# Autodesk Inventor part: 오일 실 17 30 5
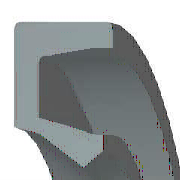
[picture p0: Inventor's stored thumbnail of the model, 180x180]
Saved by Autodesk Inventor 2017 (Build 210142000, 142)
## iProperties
IsCustomPart: 1
Created: 2012-02
Part Number: 오일 실 17 30 5
Material: 고무
Description: 오일 실 - 비스프링, 금속 케이스 GM
Document SubType Name: Modeling
Standard: JIS B 2402
Designer: mduedu
Standards Organization: JIS
Language: ko-KR
Size Designation: 17 30 5 B
Categories: <MemberInstance><Categories><Category DisplayName="샤프트 부품" InternalName="7f7aeb1f-a693-4053-b835-cee3144e0d98" Mnemonic="SHFT"><Category DisplayName="실링" Intern
Density: 0.93 g/cm^3
Appearance: Rubber-Black
Mass: 0.924459 g
Surface Area: 18.6212 cm^2
Volume: 0.994042 cm^3
Author: mduedu
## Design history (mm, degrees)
body "Solid1"
revolve "회전1" stored, may be unused: angle "d27" = 360 deg
fillet "모깎기1" dims "d28" = 0.25 (= 0.05 x b)
chamfer "모따기1" distance "d29" = 0.07143 (= 0.0142857 x b); stored, may be unused: second distance "d30" = 0.25 (= 0.05 x b), angle "d35" = 45 deg
sketch "스케치2"
  geometry: L1 (-9.367, -3.238)-(-10.233, -3.863); L2 (-8.5, -1.625)-(-9.367, -3.238); L3 (-9.15, -1)-(-8.5, -1.625); L4 (-11.317, -3.75)-(-9.15, -1); L5 (-13.075, -3.75)-(-11.317, -3.75); L6 (-14.375, -1.25)-(-13.075, -3.75); L7 (-14.375, 0)-(-14.375, -1.25); L8 (-15, 0)-(-14.375, 0); L9 (-15, -5)-(-15, 0); L10 (-11.129, -5)-(-15, -5); L11 (-10.233, -3.863)-(-11.129, -5); L12 (0, -9.6)-(0, 1.6) reference; L13 (-14, 0)-(-28, 0) reference
  constraints: 22 end point, 3 horizontal, 2 vertical, 1 parallel
  dimensions: "d2" = 5 distance of L9.start L8.start (= b); "d4" = 1 vertical distance of L8.start L3.start (= 0.2 x b); "d6" = 0.625 distance of L8.start L7.start (= 0.125 x b); "d8" = 1.25 distance of L7.start L6.start (= 0.25 x b); "d10" = 1.25 vertical distance of L5.start L9.start (= 0.25 x b); "d12" = 1.3 horizontal distance of L6.start L5.start (= 0.1 x dd - 0.1 x Diam); "d14" = 1.6129 vertical distance of L2.start L1.start (= 0.322581 x b); "d16" = 0.86667 horizontal distance of L1.start L1.end (= 0.0666667 x dd - 0.0666667 x Diam); "d18" = 0.86667 horizontal distance of L2.start L1.start (= 0.0666667 x dd - 0.0666667 x Diam); "d20" = 0.625 vertical distance of L3.start L2.start (= 0.125 x b); "d22" = 0.65 horizontal distance of L3.start L2.start (= 0.05 x dd - 0.05 x Diam); "d24" = 0.625 vertical distance of L1.start L1.end (= 0.125 x b); "d26" = 2.16667 horizontal distance of L4.start L3.start (= 0.166667 x dd - 0.166667 x Diam); "d31" = 0 distance between parallel lines of L8 L13; "d32" = 15 distance between parallel lines of L12 L9 (= 0.5 x dd); "d33" = 8.5 distance from line of L12 L2.start (= 0.5 x Diam)
other parameters: "Diam" = 17 [user parameter; used in 6 equation terms], "b" = 5 [user parameter; used in 11 equation terms], "d1" = 8 (derived), "d3" = 1.6 (derived), "d5" = 1 (derived), "d7" = 2 (derived), "d9" = 2 (derived), "d11" = 2 (derived), "d13" = 2.58065 (derived), "d15" = 1.33333 (derived), "d17" = 1.33333 (derived), "d19" = 1 (derived), "d21" = 1 (derived), "d23" = 1 (derived), "d25" = 3.33333 (derived), "d34" = 0
